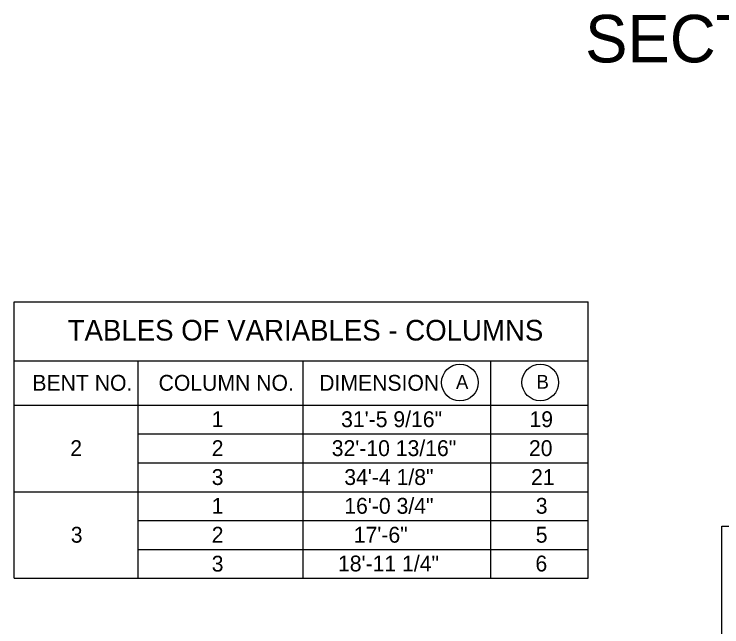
# Model space of a CAD drawing. Extents: x 1970675.2 to 1970711.3, y 796145.2 to 796167.2.
# Drawn here: x 1970699.73 to 1970705.32, y 796150.23 to 796155.06 of the extents above; entities that cross this region are included whole.
import ezdxf

# ---------------------------------------------------------------- set-up
doc = ezdxf.new("R2010")
doc.units = 0
for name, color, linetype in [('BR_AUTO DIMENSION', 7, 'Continuous'), ('BR_BORDER LINES', 7, 'Continuous'), ('BR_TABLE LINES', 7, 'Continuous'), ('BR_TEXT', 7, 'Continuous')]:
    doc.layers.add(name, color=color, linetype=linetype)

msp = doc.modelspace()

# ---------------------------------------------------------------- linework, layer by layer
at = {"layer": 'BR_AUTO DIMENSION'}
for centre in [(1970703.2506, 796152.1564), (1970703.8852, 796152.1575)]:
    msp.add_circle(centre, 0.1449, dxfattribs=at)
at = {"layer": 'BR_BORDER LINES'}
for p, q in [((1970705.3189, 796145.7463), (1970705.3189, 796151.0229)), ((1970705.3189, 796151.0229), (1970710.7358, 796151.0229))]:
    msp.add_line(p, q, dxfattribs=at)
at = {"layer": 'BR_TABLE LINES'}
for p, q in [((1970699.7306, 796152.794), (1970704.263, 796152.794)), ((1970699.7306, 796150.6117), (1970699.7306, 796152.794)), ((1970704.263, 796150.6117), (1970704.263, 796152.794)), ((1970699.7306, 796152.3292), (1970704.263, 796152.3292)), ((1970700.7089, 796150.6117), (1970700.7089, 796152.3292)), ((1970702.0132, 796150.6117), (1970702.0132, 796152.3292)), ((1970703.4942, 796150.6117), (1970703.4942, 796152.3292)), ((1970699.7306, 796151.9788), (1970704.263, 796151.9788)), ((1970700.7089, 796151.7506), (1970704.263, 796151.7506)), ((1970700.7089, 796151.5223), (1970704.263, 796151.5223)), ((1970699.7306, 796151.2953), (1970704.263, 796151.2953)), ((1970700.7089, 796151.067), (1970704.263, 796151.067)), ((1970700.7089, 796150.84), (1970704.263, 796150.84)), ((1970699.7306, 796150.6117), (1970704.263, 796150.6117))]:
    msp.add_line(p, q, dxfattribs=at)

# ---------------------------------------------------------------- texts
at = {"layer": 'BR_TEXT'}
for s, height, p in [('SECTION A-A', 0.374999, (1970704.2393, 796154.6833)), ('TABLES OF VARIABLES - COLUMNS', 0.163046, (1970700.1532, 796152.488)), ('BENT NO.', 0.125, (1970699.8747, 796152.0918)), ('COLUMN NO.', 0.125, (1970700.8711, 796152.0918)), ('DIMENSION', 0.125, (1970702.1397, 796152.0918)), ('A', 0.1087, (1970703.2199, 796152.1068)), ('B', 0.1087, (1970703.8562, 796152.1079)), ('1', 0.125, (1970701.2908, 796151.8046)), ('31\'-5 9/16"', 0.125002, (1970702.3124, 796151.8046)), ('19', 0.125, (1970703.7999, 796151.8046)), ('2', 0.125, (1970700.1738, 796151.5763)), ('2', 0.125, (1970701.2908, 796151.5763)), ('32\'-10 13/16"', 0.125002, (1970702.2384, 796151.5763)), ('20', 0.125, (1970703.7959, 796151.5763)), ('3', 0.125, (1970701.2908, 796151.3481)), ('34\'-4 1/8"', 0.125, (1970702.3376, 796151.3481)), ('21', 0.125, (1970703.8125, 796151.3481)), ('1', 0.125, (1970701.2908, 796151.1211)), ('16\'-0 3/4"', 0.125, (1970702.3376, 796151.1211)), ('3', 0.125, (1970703.8495, 796151.1211)), ('3', 0.125, (1970700.1777, 796150.8928)), ('2', 0.125, (1970701.2908, 796150.8928)), ('17\'-6"', 0.125, (1970702.4124, 796150.8928)), ('5', 0.125, (1970703.8495, 796150.8928)), ('18\'-11 1/4"', 0.125002, (1970702.288, 796150.6658)), ('6', 0.125, (1970703.8471, 796150.6658)), ('3', 0.125, (1970701.2908, 796150.6645))]:
    msp.add_text(s, height=height, dxfattribs=at).set_placement(p)

doc.saveas('drawing.dxf')
